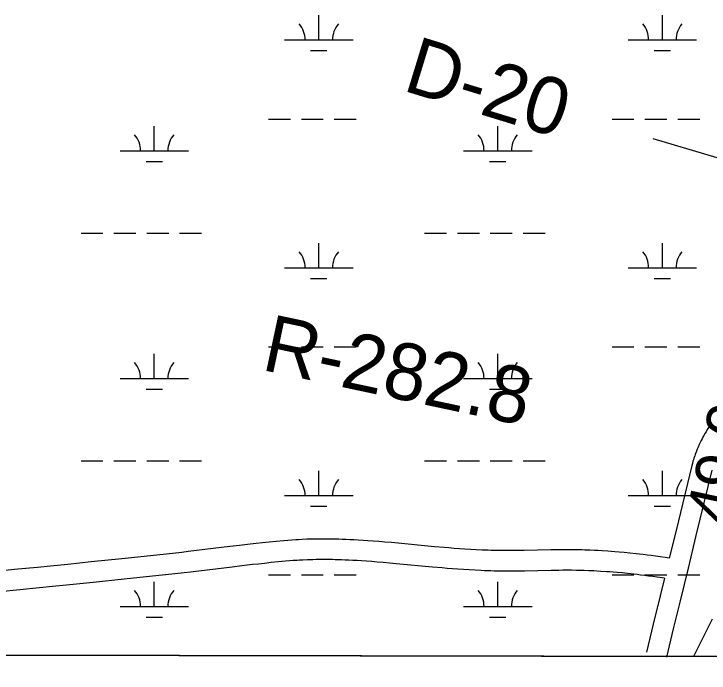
# Model space of a CAD drawing. Extents: x 3192927 to 3230760, y 831141 to 856475.
# Drawn here: x 3214685 to 3215700, y 836487 to 837449 of the extents above; entities that cross this region are included whole.
import ezdxf

# ---------------------------------------------------------------- set-up
doc = ezdxf.new("R2010")
doc.units = 0
for name, color, linetype in [('V-GRID-FRAM', 7, 'Continuous'), ('V-RIVR-RANG', 7, 'Continuous'), ('V-RIVR-RANG-IDEN', 7, 'Continuous'), ('V-ROAD-CNTR', 7, 'Continuous'), ('V-SITE-VEGE', 7, 'Continuous'), ('V-TOPO-MINR', 7, 'Continuous'), ('V-WETL-SWMP', 7, 'Continuous')]:
    doc.layers.add(name, color=color, linetype=linetype)

msp = doc.modelspace()

# ---------------------------------------------------------------- linework, layer by layer
at = {"layer": 'V-GRID-FRAM'}
msp.add_lwpolyline([(3197144.3, 854733.3), (3228527.7, 854674), (3228501.2, 836486.7), (3197102, 836546.1), (3197144.3, 854733.3)], dxfattribs=at)
at = {"layer": 'V-RIVR-RANG'}
msp.add_line((3215618.1, 837267.4), (3216615.3, 836971.9), dxfattribs=at)
at = {"layer": 'V-ROAD-CNTR'}
for points in [[(3215701.6, 836848.8), (3215699.4, 836845.4), (3215697.5, 836842.3), (3215695.7, 836839.2), (3215694, 836836.4), (3215692.5, 836833.7), (3215691.1, 836831.1), (3215689.9, 836828.7), (3215688.7, 836826.4), (3215687.7, 836824.3), (3215686.7, 836822.3), (3215685.8, 836820.3), (3215684.2, 836816.7), (3215682.8, 836813.5), (3215681.7, 836810.7), (3215680.7, 836808.2), (3215679.9, 836806), (3215679.2, 836804), (3215678.1, 836800.6), (3215677.3, 836798), (3215676.7, 836796), (3215675.9, 836793), (3215675.2, 836790.1), (3215651.9, 836694.8), (3215642.1, 836654.5)], [(3215704.3, 836782.8), (3215681, 836687.7), (3215669.4, 836640), (3215657.8, 836592.4), (3215647.8, 836551.3), (3215637.8, 836510.2)], [(3215642.1, 836654.5), (3215636, 836655.4), (3215628.7, 836656.4), (3215621.9, 836657.4), (3215615.5, 836658.2), (3215609.5, 836659), (3215603.9, 836659.7), (3215598.6, 836660.3), (3215593.6, 836660.9), (3215584.3, 836661.9), (3215576.1, 836662.7), (3215569, 836663.4), (3215562.7, 836663.9), (3215557.3, 836664.4), (3215552.4, 836664.7), (3215544.1, 836665.3), (3215537.8, 836665.6), (3215533, 836665.9), (3215525.9, 836666.2), (3215518.8, 836666.4), (3215514.7, 836666.6), (3215506.9, 836666.7), (3215499.5, 836666.8), (3215492.6, 836666.8), (3215486.2, 836666.8), (3215480.2, 836666.7), (3215468.9, 836666.6), (3215429.9, 836665.8), (3215420.2, 836665.7), (3215412.9, 836665.6), (3215407.5, 836665.6), (3215399.4, 836665.6), (3215391.3, 836665.7), (3215386.6, 836665.8), (3215382, 836665.9), (3215377.5, 836666), (3215373, 836666.2), (3215368.6, 836666.4), (3215359.9, 836666.8), (3215351.5, 836667.2), (3215343.3, 836667.8), (3215335.4, 836668.3), (3215327.7, 836668.9), (3215320.2, 836669.5), (3215313, 836670.1), (3215298.9, 836671.3), (3215246, 836676.3), (3215236, 836677.2), (3215226.6, 836678), (3215217.8, 836678.8), (3215209.6, 836679.4), (3215201.8, 836680), (3215194.6, 836680.5), (3215187.7, 836680.9), (3215181.3, 836681.2), (3215175.3, 836681.5), (3215169.7, 836681.8), (3215164.4, 836682), (3215159.4, 836682.1), (3215154.8, 836682.3), (3215150.4, 836682.4), (3215146.3, 836682.4), (3215138.6, 836682.5), (3215131.9, 836682.5), (3215126, 836682.4), (3215120.8, 836682.3), (3215116.3, 836682.2), (3215112.4, 836682.1), (3215105.5, 836681.8), (3215100.2, 836681.5), (3215096.3, 836681.3), (3215090.5, 836680.9), (3215084.6, 836680.4), (3215078.9, 836679.9), (3215067.8, 836678.9), (3215057.4, 836677.8), (3215047.6, 836676.8), (3215038.5, 836675.9), (3215029.9, 836674.9), (3215014, 836673.1), (3215000, 836671.4), (3214951.3, 836665.5), (3214939.1, 836664.1), (3214930, 836663), (3214916.3, 836661.5), (3214902.7, 836660)], [(3214902.7, 836660), (3214842.5, 836653.7), (3214797.3, 836649), (3214763.4, 836645.5), (3214738, 836643), (3214718.9, 836641.1), (3214690.3, 836638.3), (3214661.8, 836635.5)], [(3215634.9, 836625.2), (3215631.7, 836625.7), (3215624.5, 836626.7), (3215617.9, 836627.7), (3215611.6, 836628.5), (3215605.7, 836629.3), (3215600.2, 836629.9), (3215595.1, 836630.5), (3215590.3, 836631.1), (3215581.2, 836632.1), (3215573.3, 836632.9), (3215566.4, 836633.5), (3215560.3, 836634), (3215555, 836634.4), (3215550.4, 836634.8), (3215542.2, 836635.3), (3215536.1, 836635.7), (3215531.6, 836635.9), (3215524.7, 836636.2), (3215517.8, 836636.5), (3215514, 836636.6), (3215506.4, 836636.7), (3215499.3, 836636.8), (3215492.6, 836636.8), (3215486.4, 836636.8), (3215480.5, 836636.7), (3215469.4, 836636.6), (3215430.4, 836635.8), (3215420.5, 836635.7), (3215413.1, 836635.6), (3215407.6, 836635.6), (3215399.2, 836635.6), (3215390.8, 836635.7), (3215386, 836635.8), (3215381.2, 836635.9), (3215376.5, 836636), (3215371.9, 836636.2), (3215367.3, 836636.4), (3215358.3, 836636.8), (3215349.7, 836637.3), (3215341.3, 836637.8), (3215333.2, 836638.4), (3215325.3, 836639), (3215317.8, 836639.6), (3215310.4, 836640.2), (3215296.2, 836641.5), (3215243.2, 836646.4), (3215233.3, 836647.3), (3215224.1, 836648.1), (3215215.4, 836648.9), (3215207.3, 836649.5), (3215199.7, 836650), (3215192.6, 836650.5), (3215186, 836650.9), (3215179.7, 836651.3), (3215173.9, 836651.6), (3215168.4, 836651.8), (3215163.3, 836652), (3215158.5, 836652.2), (3215154, 836652.3), (3215149.8, 836652.4), (3215145.9, 836652.4), (3215138.5, 836652.5), (3215132.1, 836652.5), (3215126.4, 836652.4), (3215121.5, 836652.3), (3215117.2, 836652.2), (3215113.5, 836652.1), (3215106.9, 836651.8), (3215101.9, 836651.6), (3215098.3, 836651.3), (3215092.7, 836651), (3215087.2, 836650.5), (3215081.6, 836650), (3215070.6, 836649), (3215060.4, 836648), (3215050.8, 836647), (3215041.8, 836646), (3215033.3, 836645.1), (3215017.5, 836643.3), (3215003.6, 836641.6), (3214954.8, 836635.7), (3214942.6, 836634.3), (3214933.4, 836633.2), (3214919.6, 836631.6), (3214905.9, 836630.1)], [(3214905.8, 836630.1), (3214845.6, 836623.8), (3214800.4, 836619.1), (3214766.4, 836615.7), (3214741, 836613.1), (3214721.9, 836611.2), (3214693.2, 836608.4), (3214664.6, 836605.6)], [(3215634.9, 836625.3), (3215628.7, 836599.5), (3215618.7, 836558.4), (3215608.7, 836517.2)]]:
    msp.add_lwpolyline(points, dxfattribs=at)
at = {"layer": 'V-SITE-VEGE'}
msp.add_line((3211708, 836518.5), (3215770.2, 836510.8), dxfattribs=at)
at = {"layer": 'V-TOPO-MINR'}
msp.add_lwpolyline([(3215704.6, 836565.3), (3215677.3, 836511)], dxfattribs=at)
at = {"layer": 'V-WETL-SWMP'}
for p, q in [((3215130, 837411.2), (3215130, 837447.2)), ((3215631.9, 837411.2), (3215631.9, 837447.2)), ((3215080, 837411.2), (3215180, 837411.2)), ((3215581.9, 837411.2), (3215681.9, 837411.2)), ((3215118, 837395.8), (3215142, 837395.8)), ((3215619.9, 837395.8), (3215643.9, 837395.8)), ((3215056.6, 837295.8), (3215088.6, 837295.8)), ((3215104.6, 837295.8), (3215136.6, 837295.8)), ((3215152.6, 837295.8), (3215184.6, 837295.8)), ((3215558.5, 837295.8), (3215590.5, 837295.8)), ((3215606.5, 837295.8), (3215638.5, 837295.8)), ((3215654.5, 837295.8), (3215686.5, 837295.8)), ((3214889.6, 837249.4), (3214889.6, 837285.4)), ((3215391.5, 837249.4), (3215391.5, 837285.4)), ((3214839.6, 837249.4), (3214939.6, 837249.4)), ((3215341.5, 837249.4), (3215441.5, 837249.4)), ((3214877.6, 837233.9), (3214901.6, 837233.9)), ((3215379.5, 837233.9), (3215403.5, 837233.9)), ((3214782.7, 837129.3), (3214814.7, 837129.3)), ((3214830.7, 837129.3), (3214862.7, 837129.3)), ((3214878.7, 837129.3), (3214910.7, 837129.3)), ((3214926.7, 837129.3), (3214958.7, 837129.3)), ((3215284.6, 837129.3), (3215316.6, 837129.3)), ((3215332.6, 837129.3), (3215364.6, 837129.3)), ((3215380.6, 837129.3), (3215412.6, 837129.3)), ((3215428.6, 837129.3), (3215460.6, 837129.3)), ((3215130, 837078.6), (3215130, 837114.6)), ((3215631.9, 837078.6), (3215631.9, 837114.6)), ((3215080, 837078.6), (3215180, 837078.6)), ((3215581.9, 837078.6), (3215681.9, 837078.6)), ((3215118, 837063.1), (3215142, 837063.1)), ((3215619.9, 837063.1), (3215643.9, 837063.1)), ((3215056.6, 836963.1), (3215088.6, 836963.1)), ((3215104.6, 836963.1), (3215136.6, 836963.1)), ((3215152.6, 836963.1), (3215184.6, 836963.1)), ((3215558.5, 836963.1), (3215590.5, 836963.1)), ((3215606.5, 836963.1), (3215638.5, 836963.1)), ((3215654.5, 836963.1), (3215686.5, 836963.1)), ((3214889.6, 836916.7), (3214889.6, 836952.7)), ((3215391.5, 836916.7), (3215391.5, 836952.7)), ((3214839.6, 836916.7), (3214939.6, 836916.7)), ((3215341.5, 836916.7), (3215441.5, 836916.7)), ((3214877.6, 836901.3), (3214901.6, 836901.3)), ((3215379.5, 836901.3), (3215403.5, 836901.3)), ((3214782.7, 836796.6), (3214814.7, 836796.6)), ((3214830.7, 836796.6), (3214862.7, 836796.6)), ((3214878.7, 836796.6), (3214910.7, 836796.6)), ((3214926.7, 836796.6), (3214958.7, 836796.6)), ((3215284.6, 836796.6), (3215316.6, 836796.6)), ((3215332.6, 836796.6), (3215364.6, 836796.6)), ((3215380.6, 836796.6), (3215412.6, 836796.6)), ((3215428.6, 836796.6), (3215460.6, 836796.6)), ((3215130, 836745.9), (3215130, 836781.9)), ((3215631.9, 836745.9), (3215631.9, 836781.9)), ((3215080, 836745.9), (3215180, 836745.9)), ((3215581.9, 836745.9), (3215681.9, 836745.9)), ((3215118, 836730.4), (3215142, 836730.4)), ((3215619.9, 836730.4), (3215643.9, 836730.4)), ((3215056.6, 836630.4), (3215088.6, 836630.4)), ((3215104.6, 836630.4), (3215136.6, 836630.4)), ((3215152.6, 836630.4), (3215184.6, 836630.4)), ((3215558.5, 836630.4), (3215590.5, 836630.4)), ((3215606.5, 836630.4), (3215638.5, 836630.4)), ((3215654.5, 836630.4), (3215686.5, 836630.4)), ((3214889.6, 836584), (3214889.6, 836620)), ((3215391.5, 836584), (3215391.5, 836620)), ((3214839.6, 836584), (3214939.6, 836584)), ((3215341.5, 836584), (3215441.5, 836584)), ((3214877.6, 836568.6), (3214901.6, 836568.6)), ((3215379.5, 836568.6), (3215403.5, 836568.6)), ((3211708, 836518.5), (3215720.4, 836510.9))]:
    msp.add_line(p, q, dxfattribs=at)
for centre, start, end in [((3215074.8, 837411.7), 359.2282, 40.7718), ((3215185.3, 837411.7), 139.2282, 180.7718), ((3215576.7, 837411.7), 359.2282, 40.7718), ((3215687.2, 837411.7), 139.2282, 180.7718), ((3214834.3, 837249.8), 359.2282, 40.7718), ((3214944.8, 837249.8), 139.2282, 180.7718), ((3215336.2, 837249.8), 359.2282, 40.7718), ((3215446.7, 837249.8), 139.2282, 180.7718), ((3215074.8, 837079), 359.2282, 40.7718), ((3215185.3, 837079), 139.2282, 180.7718), ((3215576.7, 837079), 359.2282, 40.7718), ((3215687.2, 837079), 139.2282, 180.7718), ((3214834.3, 836917.2), 359.2282, 40.7718), ((3214944.8, 836917.2), 139.2282, 180.7718), ((3215336.2, 836917.2), 359.2282, 40.7718), ((3215446.7, 836917.2), 139.2282, 180.7718), ((3215074.8, 836746.3), 359.2282, 40.7718), ((3215185.3, 836746.3), 139.2282, 180.7718), ((3215576.7, 836746.3), 359.2282, 40.7718), ((3215687.2, 836746.3), 139.2282, 180.7718), ((3214834.3, 836584.5), 359.2282, 40.7718), ((3214944.8, 836584.5), 139.2282, 180.7718), ((3215336.2, 836584.5), 359.2282, 40.7718), ((3215446.7, 836584.5), 139.2282, 180.7718)]:
    msp.add_arc(centre, 35.2, start, end, dxfattribs=at)

# ---------------------------------------------------------------- texts
at = {"layer": 'V-RIVR-RANG'}
msp.add_text('49.0', height=67, rotation=77.8283, dxfattribs=at).set_placement((3215731.4, 836701.3))
at = {"layer": 'V-RIVR-RANG-IDEN'}
for s, rotation, p in [('D-20', 342.9468, (3215250.8, 837338)), ('R-282.8', 347.9666, (3215044.5, 836929.9))]:
    msp.add_text(s, height=83, rotation=rotation, dxfattribs=at).set_placement(p)

doc.saveas('drawing.dxf')
